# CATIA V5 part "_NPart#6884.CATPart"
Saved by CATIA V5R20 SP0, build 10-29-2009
Part number: Junta tórica
Revision: ANY
Definition: UNKNOWN
Nomenclature: Junta tórica
Source: Unknown
Bounding box of the stored display mesh (mm): x -10.34 to 10.34, y -1 to 1, z -10.5 to 10.5
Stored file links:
  C:\Users\Utente\Desktop\IO LAVORO\3D X SITO CF\CUMSA\3D files AE\AE 052430\_NPart#6884.CATPart
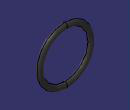
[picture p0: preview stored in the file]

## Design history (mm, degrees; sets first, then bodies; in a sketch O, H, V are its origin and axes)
Body1 "Revolución1" (main body)
  Solid1: solid without history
